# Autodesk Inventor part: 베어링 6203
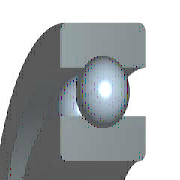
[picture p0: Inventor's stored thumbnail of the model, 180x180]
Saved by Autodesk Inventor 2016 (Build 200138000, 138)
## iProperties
IsCustomPart: 0
Company: 한국ATC센터
Created: 2015-11
Part Number: 베어링 6203
Material: 강철, 연강
Description: 깊은 그루브 볼 베어링
Document SubType Name: Modeling
Standard: KS B 2023
Designer: mdu
Standards Organization: KS
Language: ko-KR
Size Designation: 6203 - 17 x 40 x 12
Categories: <MemberInstance><Categories><Category DisplayName="샤프트 부품" InternalName="7f7aeb1f-a693-4053-b835-cee3144e0d98" Mnemonic="SHFT"><Category DisplayName="베어링" Inter
Density: 7.86 g/cm^3
Appearance: 노란색
Mass: 64.9809 g
Surface Area: 64.3582 cm^2
Volume: 8.26729 cm^3
Author: mdu
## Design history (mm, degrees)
sketch "스케치" dims "d0" = 5.98 (= -0.26 x WD + 0.26 x BD)
  geometry: L1 (3.01, 14.25)-(8.99, 14.25); L2 (6, 14.25)-(6, 11.26); L3 (6, 14.25)-(6, 17.24); L4 (3.778, 12.249)-(0, 12.249); L5 (0, 8.5)-(12, 8.5); L6 (3.778, 16.251)-(0, 16.251); L7 (0, 20)-(12, 20); L8 (12, 8.5)-(12, 12.249); L9 (8.222, 12.249)-(12, 12.249); L10 (8.222, 16.251)-(12, 16.251); L11 (12, 20)-(12, 16.251); L12 (-1.4, 0)-(8.4, 0) reference; L13 (0, -0.3)-(0, 5.3) reference
  constraints: 22 end point, 4 point on line, 2 collinear, 2 perpendicular, 2 symmetric about line, 1 midpoint, 1 parallel, 14 other
  dimensions: "d9" = 17 diameter of L5 L12 (= WD); "d11" = 40 diameter of L7 L12 (= BD); "d12" = 12 distance between parallel lines of L8 L13 (= KB); "d13" = 24.498 diameter of L9 L12 (= 0.326 x BD + 0.674 x WD)
revolve "본체" stored, may be unused: angle "d6" = 90 deg
revolve "볼" stored, may be unused: angle "d7" = 90 deg
pattern_circular "IDS_ARRAYBALL[SIMPL:T]" dims angle "d3" = 360 deg
body "Solid1"
fillet "모깎기1" dims "d1" = 0.6 (= KRS)
other parameters: "WD" = 17 [user parameter; used in 5 equation terms], "BD" = 40 [user parameter; used in 5 equation terms], "KB" = 12 [user parameter; used in 1 equation term], "KRS" = 0.6 [user parameter; used in 1 equation term], "d4" = 0, "d5" = 0, "d8" = 0, "d14" = 0, "d15" = 0, "BBA" = 0 [user parameter], "BC0" = 4750000 [user parameter], "BC" = 9560000 [user parameter], "WR" = 8.5 (= 0.5 x WD) [user parameter]
